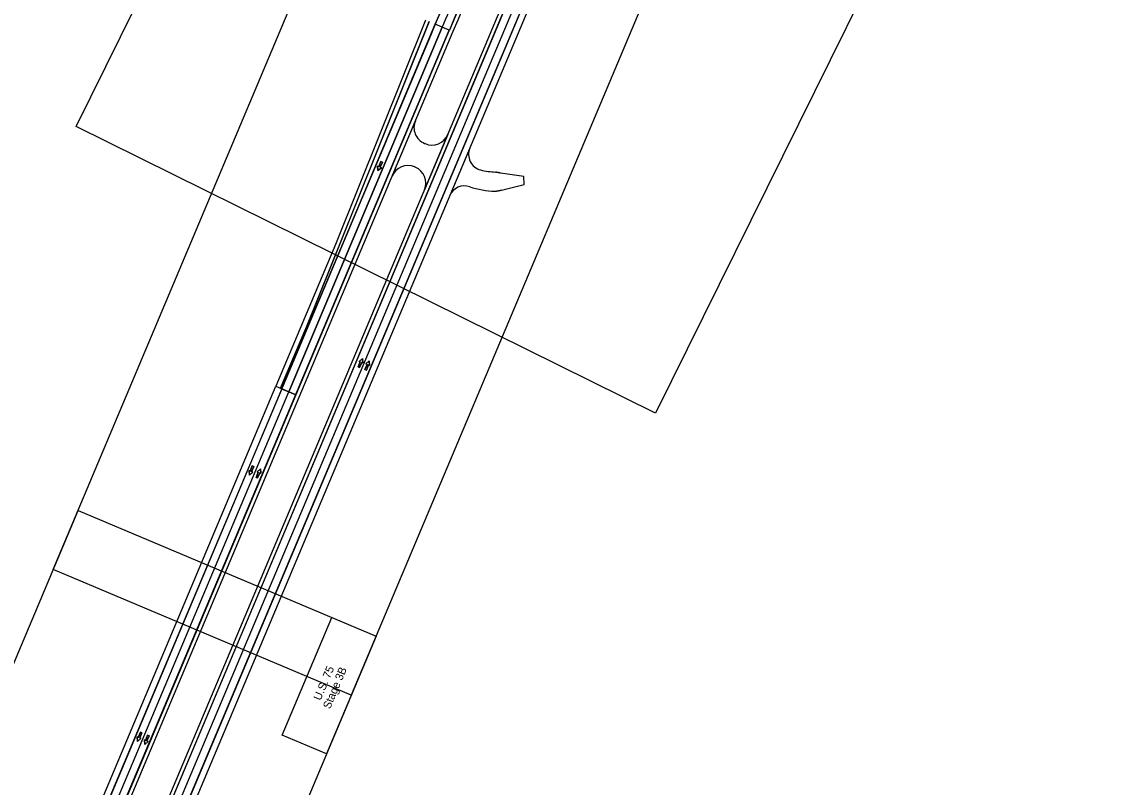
# Model space of a CAD drawing. Extents: x 14104283 to 14120882, y 8635219 to 8671666.
# Drawn here: x 14118007 to 14119692, y 8666822 to 8668018 of the extents above; entities that cross this region are included whole.
import ezdxf

# ---------------------------------------------------------------- set-up
doc = ezdxf.new("R2010")
doc.units = 0
for name, color, linetype in [('Cell', 7, 'Continuous'), ('Default', 7, 'Continuous'), ('dsnNonPlotable', 7, 'Continuous'), ('dsnPaintExistingBrokenLaneLineWhite', 7, 'Continuous'), ('dsnPaintExistingEdgeLineLeftYellow', 7, 'Continuous'), ('dsnPaintExistingEdgeLineRightWhite', 7, 'Continuous'), ('dsnShadingPaved', 7, 'Continuous'), ('dsnStgShadingPrevPav', 7, 'Continuous'), ('dsnTextOverlapEven', 7, 'Continuous'), ('Level 2', 7, 'Continuous'), ('Level 5', 7, 'Continuous')]:
    doc.layers.add(name, color=color, linetype=linetype)

msp = doc.modelspace()

# ---------------------------------------------------------------- linework, layer by layer
at = {"layer": 'Cell'}
for points in [[(14118535, 8667477.3), (14118532.6, 8667478.3), (14118536, 8667486.4), (14118534.2, 8667487.1), (14118539.5, 8667491.7), (14118540, 8667484.7), (14118538.3, 8667485.4)], [(14118545.6, 8667473.4), (14118543.3, 8667474.4), (14118546.6, 8667482.4), (14118544.9, 8667483.2), (14118550.1, 8667487.8), (14118550.6, 8667480.8), (14118548.9, 8667481.5)], [(14118367.3, 8667323.8), (14118369.6, 8667322.9), (14118366.3, 8667314.8), (14118368, 8667314.1), (14118362.8, 8667309.5), (14118362.2, 8667316.5), (14118364, 8667315.7)], [(14118375.7, 8667305), (14118373.4, 8667305.9), (14118376.7, 8667314), (14118375, 8667314.7), (14118380.3, 8667319.3), (14118380.8, 8667312.3), (14118379, 8667313.1)], [(14118192.7, 8666908), (14118195, 8666907.1), (14118191.7, 8666899), (14118193.4, 8666898.3), (14118188.1, 8666893.7), (14118187.6, 8666900.6), (14118189.3, 8666899.9)], [(14118203.7, 8666903.4), (14118206, 8666902.4), (14118202.7, 8666894.3), (14118204.5, 8666893.6), (14118199.2, 8666889), (14118198.7, 8666896), (14118200.4, 8666895.3)]]:
    msp.add_lwpolyline(points, close=True, dxfattribs=at)
for points in [[(14118538.3, 8667485.4), (14118540, 8667484.7), (14118539.5, 8667491.7), (14118534.2, 8667487.1), (14118536, 8667486.4), (14118532.6, 8667478.3), (14118535, 8667477.3), (14118538.3, 8667485.4)], [(14118548.9, 8667481.5), (14118550.6, 8667480.8), (14118550.1, 8667487.8), (14118544.9, 8667483.2), (14118546.6, 8667482.4), (14118543.3, 8667474.4), (14118545.6, 8667473.4), (14118548.9, 8667481.5)], [(14118364, 8667315.7), (14118362.2, 8667316.5), (14118362.8, 8667309.5), (14118368, 8667314.1), (14118366.3, 8667314.8), (14118369.6, 8667322.9), (14118367.3, 8667323.8), (14118364, 8667315.7)], [(14118379, 8667313.1), (14118380.8, 8667312.3), (14118380.3, 8667319.3), (14118375, 8667314.7), (14118376.7, 8667314), (14118373.4, 8667305.9), (14118375.7, 8667305), (14118379, 8667313.1)], [(14118189.3, 8666899.9), (14118187.6, 8666900.6), (14118188.1, 8666893.7), (14118193.4, 8666898.3), (14118191.7, 8666899), (14118195, 8666907.1), (14118192.7, 8666908), (14118189.3, 8666899.9)], [(14118200.4, 8666895.3), (14118198.7, 8666896), (14118199.2, 8666889), (14118204.5, 8666893.6), (14118202.7, 8666894.3), (14118206, 8666902.4), (14118203.7, 8666903.4), (14118200.4, 8666895.3)]]:
    msp.add_lwpolyline(points, dxfattribs=at)
at = {"layer": 'Default'}
for p, q in [((14118528.4, 8667730.9), (14118643.5, 8668017.6)), ((14118675.1, 8668004.3), (14118653, 8668013.6)), ((14118646.5, 8667998.1), (14118579.3, 8667838.5)), ((14118576.7, 8667832.4), (14118534.2, 8667731.7)), ((14118534.2, 8667731.7), (14118412.9, 8667443.5)), ((14118412.9, 8667443.5), (14118528.4, 8667730.9))]:
    msp.add_line(p, q, dxfattribs=at)
for points in [[(14118653, 8668013.6), (14118412.9, 8667444.4), (14118424.3, 8667439.6), (14118664.1, 8668009)], [(14118435.4, 8667434.9), (14118675.1, 8668004.3), (14118664.1, 8668009), (14118424.2, 8667439.7)]]:
    msp.add_lwpolyline(points, close=True, dxfattribs=at)
for centre, radius, start in [((14123733, 8665874.4), 5488, 152.6921), ((14123733, 8665874.4), 5512, 153.1692), ((14123265.6, 8666052.9), 5012, 155.8003)]:
    msp.add_arc(centre, radius, start, 157.1633, dxfattribs=at)
at = {"layer": 'dsnNonPlotable'}
for points in [[(14118092, 8667853.7), (14118786.8, 8669258.8), (14119692.1, 8668811.2), (14118997.4, 8667406.1)], [(14118056.5, 8667161.9), (14118665.1, 8668606.4), (14119130.4, 8668410.4), (14118521.9, 8666965.8)], [(14117486.7, 8665809.5), (14118095.3, 8667254.1), (14118560.7, 8667058), (14117952.1, 8665613.5)]]:
    msp.add_lwpolyline(points, close=True, dxfattribs=at)
at = {"layer": 'dsnPaintExistingBrokenLaneLineWhite'}
for p, q in [((14114932.5, 8658913.4), (14118863.7, 8668248.6)), ((14118664.1, 8668009), (14118424.3, 8667439.6)), ((14110829.5, 8649404.5), (14118424.3, 8667439.6))]:
    msp.add_line(p, q, dxfattribs=at)
msp.add_arc((14123733, 8665874.4), 5500, 152.6921, 157.1633, dxfattribs=at)
at = {"layer": 'dsnPaintExistingEdgeLineLeftYellow'}
for p, q in [((14115900.9, 8661244), (14118817.4, 8668169.6)), ((14118675.1, 8668004.3), (14118435.4, 8667434.9)), ((14118435.4, 8667434.9), (14115816.1, 8661215.2))]:
    msp.add_line(p, q, dxfattribs=at)
msp.add_arc((14123733, 8665874.4), 5488, 152.6921, 157.1633, dxfattribs=at)
at = {"layer": 'dsnPaintExistingEdgeLineRightWhite'}
for p, q in [((14110924.4, 8649364.5), (14118874.7, 8668243.7)), ((14118643.5, 8668017.6), (14118412.9, 8667444.4)), ((14118413.2, 8667444.3), (14115798.8, 8661235.7))]:
    msp.add_line(p, q, dxfattribs=at)
at = {"layer": 'dsnShadingPaved'}
msp.add_line((14118435.4, 8667434.9), (14118413.2, 8667444.3), dxfattribs=at)
msp.add_lwpolyline([(14118227.7, 8666769.2), (14118817.4, 8668169.6), (14118839.4, 8668160), (14118249.8, 8666759.9)], close=True, dxfattribs=at)
for points in [[(14118413.2, 8667444.3), (14110818.4, 8649409.2), (14109142.6, 8645431.4)], [(14109164.7, 8645422.1), (14110840.5, 8649399.8), (14118435.4, 8667434.9)]]:
    msp.add_lwpolyline(points, dxfattribs=at)
at = {"layer": 'dsnStgShadingPrevPav'}
for p, q in [((14115895.6, 8661246.8), (14118811.5, 8668171)), ((14118848.4, 8668155.5), (14115932.5, 8661231.3)), ((14118653, 8668013.6), (14115794, 8661224.5)), ((14118652.6, 8668013.1), (14118415.9, 8667450.9)), ((14118458, 8667555.6), (14118643.5, 8668017.6)), ((14118458, 8667555.6), (14118643.5, 8668017.6)), ((14118638, 8668019.9), (14118497.2, 8667669.3)), ((14115816.1, 8661215.2), (14118675.1, 8668004.3)), ((14115816.1, 8661215.2), (14118675.1, 8668004.3)), ((14118680.7, 8668002), (14115821.7, 8661212.9)), ((14118585.6, 8667776.2), (14118622.1, 8667862.8)), ((14118672.7, 8667841.4), (14118636.3, 8667754.8)), ((14118636.5, 8667827.4), (14118637.4, 8667827)), ((14118707.1, 8667819.9), (14118675.9, 8667745.8)), ((14118621.9, 8667790.2), (14118620.9, 8667790.6)), ((14118791.6, 8667775.6), (14118755.1, 8667781)), ((14118792.2, 8667763.1), (14118791.6, 8667775.6)), ((14118756.4, 8667754.5), (14118792.2, 8667763.1)), ((14118497.2, 8667669.3), (14118404, 8667448.1)), ((14118411.4, 8667445), (14118458, 8667555.6)), ((14118411.4, 8667445), (14118458, 8667555.6)), ((14118415.9, 8667450.9), (14118413.1, 8667444.3)), ((14110809.2, 8649413), (14118404, 8667448.1)), ((14118413.2, 8667444.3), (14110818.4, 8649409.2)), ((14118404, 8667448.1), (14118411.4, 8667445)), ((14118404, 8667448.1), (14118413.2, 8667444.3)), ((14118413.2, 8667444.3), (14118411.4, 8667445))]:
    msp.add_line(p, q, dxfattribs=at)
for centre, radius, start, end in [((14123733, 8665874.4), 5512, 146.4256, 157.1633), ((14123733, 8665874.4), 5488, 146.4212, 157.1633), ((14123732.6, 8665873.8), 5512, 150.362, 157.1633), ((14123733, 8665874.4), 5488, 150.6709, 157.1633), ((14123733, 8665874.4), 5482, 150.671, 157.1633), ((14118646.9, 8667852.3), 27, 157.1633, 247.1633), ((14118647.9, 8667851.9), 27, 247.1633, 337.1633), ((14118730.1, 8667810.2), 25, 157.1633, 255.6089), ((14118610.5, 8667765.7), 27, 67.1633, 157.1633), ((14118611.4, 8667765.3), 27, 337.1633, 67.1633), ((14118750, 8667887.7), 105, 255.6089, 268.5297), ((14118698.9, 8667736.1), 25, 71.3746, 157.1633), ((14118750, 8667887.7), 135, 251.3746, 268.5297)]:
    msp.add_arc(centre, radius, start, end, dxfattribs=at)
for points in [[(14118755.1, 8667781), (14118755, 8667781.1), (14118754.7, 8667781.1), (14118754.3, 8667781.2), (14118754, 8667781.2), (14118753.6, 8667781.3), (14118753.2, 8667781.4), (14118752.8, 8667781.5), (14118752.4, 8667781.6), (14118752, 8667781.6), (14118751.6, 8667781.7), (14118751.2, 8667781.8), (14118750.8, 8667781.9), (14118750.4, 8667782), (14118750, 8667782.1), (14118749.6, 8667782.2), (14118749.2, 8667782.2), (14118748.8, 8667782.3), (14118748.5, 8667782.4), (14118748.1, 8667782.5), (14118747.7, 8667782.6), (14118747.4, 8667782.7), (14118747.3, 8667782.7)], [(14118746.5, 8667752.7), (14118746.7, 8667752.8), (14118747, 8667752.8), (14118747.5, 8667752.9), (14118748, 8667752.9), (14118748.5, 8667753), (14118749, 8667753.1), (14118749.5, 8667753.2), (14118750, 8667753.3), (14118750.5, 8667753.4), (14118751, 8667753.4), (14118751.5, 8667753.5), (14118752, 8667753.6), (14118752.5, 8667753.7), (14118753, 8667753.8), (14118753.5, 8667753.9), (14118754, 8667754), (14118754.5, 8667754.1), (14118755, 8667754.2), (14118755.4, 8667754.3), (14118755.9, 8667754.4), (14118756.3, 8667754.5), (14118756.4, 8667754.5)]]:
    msp.add_open_spline(points, degree=3, dxfattribs=at)
at = {"layer": 'dsnTextOverlapEven'}
for points in [[(14118560.7, 8667058), (14118483.3, 8666874.4), (14118414.2, 8666903.5), (14118491.6, 8667087.1)], [(14118414.2, 8666903.5), (14118491.6, 8667087.1), (14118560.7, 8667058), (14118483.3, 8666874.4)]]:
    msp.add_lwpolyline(points, close=True, dxfattribs=at)
at = {"layer": 'Level 2'}
msp.add_lwpolyline([(14118570.5, 8667798.3), (14118568.2, 8667799.3), (14118564.8, 8667791.2), (14118563.1, 8667792), (14118563.6, 8667785), (14118568.9, 8667789.5), (14118567.1, 8667790.3)], close=True, dxfattribs=at)
at = {"layer": 'Level 5'}
msp.add_lwpolyline([(14118567.1, 8667790.3), (14118568.9, 8667789.5), (14118563.6, 8667785), (14118563.1, 8667792), (14118564.8, 8667791.2), (14118568.2, 8667799.3), (14118570.5, 8667798.3), (14118567.1, 8667790.3)], dxfattribs=at)

# ---------------------------------------------------------------- texts
at = {"layer": 'dsnTextOverlapEven'}
for s, p in [('U.S. 75', (14118473.9, 8666956.5)), ('Stage 3B', (14118488.6, 8666943.2))]:
    msp.add_text(s, height=12.5, rotation=67.1547, dxfattribs=at).set_placement(p)

doc.saveas('drawing.dxf')
